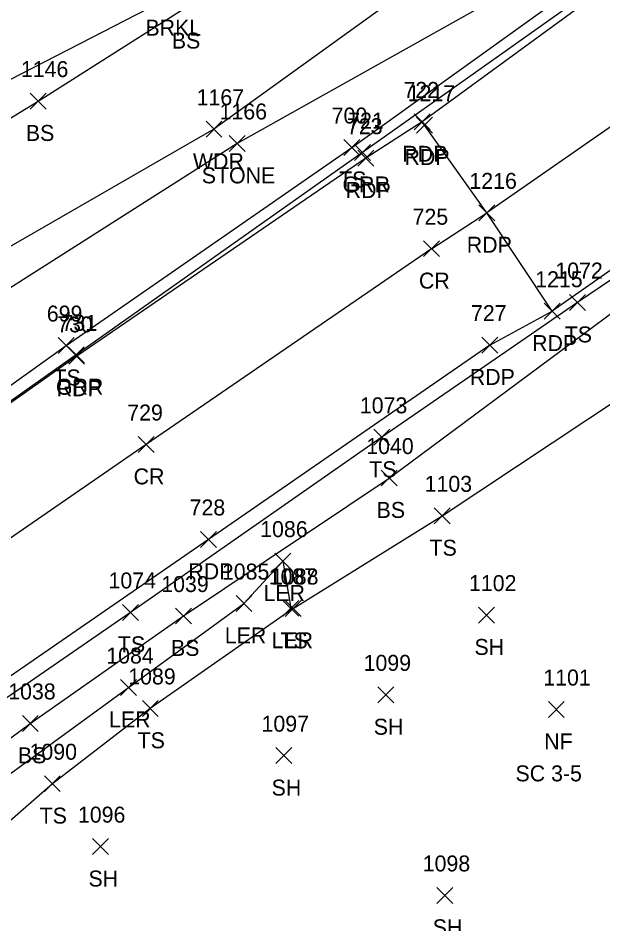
# Model space of a CAD drawing. Extents: x 1528286 to 1556263, y 492387 to 508952.
# Drawn here: x 1528736.9 to 1528810.2, y 492794 to 492907.5 of the extents above; entities that cross this region are included whole.
import ezdxf

# ---------------------------------------------------------------- set-up
doc = ezdxf.new("R2010")
doc.units = 0
for name, color, linetype in [('L_A', 7, 'Continuous'), ('L_C', 7, 'Continuous'), ('L_I', 7, 'Continuous'), ('L_TIC', 7, 'Continuous'), ('LARO', 7, 'Continuous'), ('LASF', 7, 'Continuous'), ('LAWA', 7, 'Continuous'), ('LAWE', 7, 'Continuous'), ('LELB', 7, 'Continuous'), ('P_A', 7, 'Continuous'), ('P_I', 7, 'Continuous'), ('P_TIC', 7, 'Continuous'), ('PET', 7, 'Continuous'), ('PRC', 7, 'Continuous'), ('R_A', 7, 'Continuous'), ('R_I', 7, 'Continuous'), ('R_TIC', 7, 'Continuous'), ('RGR', 7, 'Continuous')]:
    doc.layers.add(name, color=color, linetype=linetype)

msp = doc.modelspace()

# ---------------------------------------------------------------- linework, layer by layer
at = {"layer": 'L_TIC'}
for points in [[(1528738.42, 492896.09), (1528740.42, 492898.09)], [(1528740.42, 492896.09), (1528738.42, 492898.09)], [(1528738.42, 492896.09), (1528740.42, 492898.09)], [(1528740.42, 492896.09), (1528738.42, 492898.09)], [(1528760.44, 492892.56), (1528762.44, 492894.56)], [(1528762.44, 492892.56), (1528760.44, 492894.56)], [(1528760.44, 492892.56), (1528762.44, 492894.56)], [(1528762.44, 492892.56), (1528760.44, 492894.56)], [(1528763.36, 492890.78), (1528765.36, 492892.78)], [(1528765.36, 492890.78), (1528763.36, 492892.78)], [(1528763.36, 492890.78), (1528765.36, 492892.78)], [(1528765.36, 492890.78), (1528763.36, 492892.78)], [(1528777.71, 492890.27), (1528779.71, 492892.27)], [(1528779.71, 492890.27), (1528777.71, 492892.27)], [(1528777.71, 492890.27), (1528779.71, 492892.27)], [(1528779.71, 492890.27), (1528777.71, 492892.27)], [(1528805.99, 492870.86), (1528807.99, 492872.86)], [(1528807.99, 492870.86), (1528805.99, 492872.86)], [(1528805.99, 492870.86), (1528807.99, 492872.86)], [(1528807.99, 492870.86), (1528805.99, 492872.86)], [(1528741.91, 492865.47), (1528743.91, 492867.47)], [(1528743.91, 492865.47), (1528741.91, 492867.47)], [(1528741.91, 492865.47), (1528743.91, 492867.47)], [(1528743.91, 492865.47), (1528741.91, 492867.47)], [(1528781.49, 492853.98), (1528783.49, 492855.98)], [(1528783.49, 492853.98), (1528781.49, 492855.98)], [(1528781.49, 492853.98), (1528783.49, 492855.98)], [(1528783.49, 492853.98), (1528781.49, 492855.98)], [(1528782.38, 492848.88), (1528784.38, 492850.88)], [(1528784.38, 492848.88), (1528782.38, 492850.88)], [(1528782.38, 492848.88), (1528784.38, 492850.88)], [(1528784.38, 492848.88), (1528782.38, 492850.88)], [(1528789.05, 492844.15), (1528791.05, 492846.15)], [(1528791.05, 492844.15), (1528789.05, 492846.15)], [(1528789.05, 492844.15), (1528791.05, 492846.15)], [(1528791.05, 492844.15), (1528789.05, 492846.15)], [(1528769.06, 492838.48), (1528771.06, 492840.48)], [(1528771.06, 492838.48), (1528769.06, 492840.48)], [(1528769.06, 492838.48), (1528771.06, 492840.48)], [(1528771.06, 492838.48), (1528769.06, 492840.48)], [(1528764.2, 492833.16), (1528766.2, 492835.16)], [(1528766.2, 492833.16), (1528764.2, 492835.16)], [(1528764.2, 492833.16), (1528766.2, 492835.16)], [(1528766.2, 492833.16), (1528764.2, 492835.16)], [(1528749.99, 492832.05), (1528751.99, 492834.05)], [(1528751.99, 492832.05), (1528749.99, 492834.05)], [(1528749.99, 492832.05), (1528751.99, 492834.05)], [(1528751.99, 492832.05), (1528749.99, 492834.05)], [(1528756.61, 492831.6), (1528758.61, 492833.6)], [(1528758.61, 492831.6), (1528756.61, 492833.6)], [(1528756.61, 492831.6), (1528758.61, 492833.6)], [(1528758.61, 492831.6), (1528756.61, 492833.6)], [(1528770.07, 492832.56), (1528772.07, 492834.56)], [(1528772.07, 492832.56), (1528770.07, 492834.56)], [(1528770.07, 492832.56), (1528772.07, 492834.56)], [(1528772.07, 492832.56), (1528770.07, 492834.56)], [(1528770.37, 492832.54), (1528772.37, 492834.54)], [(1528772.37, 492832.54), (1528770.37, 492834.54)], [(1528770.37, 492832.54), (1528772.37, 492834.54)], [(1528772.37, 492832.54), (1528770.37, 492834.54)], [(1528770.37, 492832.54), (1528772.37, 492834.54)], [(1528772.37, 492832.54), (1528770.37, 492834.54)], [(1528770.37, 492832.54), (1528772.37, 492834.54)], [(1528772.37, 492832.54), (1528770.37, 492834.54)], [(1528794.6, 492831.72), (1528796.6, 492833.72)], [(1528796.6, 492831.72), (1528794.6, 492833.72)], [(1528794.6, 492831.72), (1528796.6, 492833.72)], [(1528796.6, 492831.72), (1528794.6, 492833.72)], [(1528749.71, 492822.64), (1528751.71, 492824.64)], [(1528751.71, 492822.64), (1528749.71, 492824.64)], [(1528749.71, 492822.64), (1528751.71, 492824.64)], [(1528751.71, 492822.64), (1528749.71, 492824.64)], [(1528781.97, 492821.73), (1528783.97, 492823.73)], [(1528783.97, 492821.73), (1528781.97, 492823.73)], [(1528781.97, 492821.73), (1528783.97, 492823.73)], [(1528783.97, 492821.73), (1528781.97, 492823.73)], [(1528752.46, 492820.03), (1528754.46, 492822.03)], [(1528754.46, 492820.03), (1528752.46, 492822.03)], [(1528752.46, 492820.03), (1528754.46, 492822.03)], [(1528754.46, 492820.03), (1528752.46, 492822.03)], [(1528803.35, 492819.89), (1528805.35, 492821.89)], [(1528805.35, 492819.89), (1528803.35, 492821.89)], [(1528803.35, 492819.89), (1528805.35, 492821.89)], [(1528805.35, 492819.89), (1528803.35, 492821.89)], [(1528737.42, 492818.15), (1528739.42, 492820.15)], [(1528739.42, 492818.15), (1528737.42, 492820.15)], [(1528737.42, 492818.15), (1528739.42, 492820.15)], [(1528739.42, 492818.15), (1528737.42, 492820.15)], [(1528769.18, 492814.11), (1528771.18, 492816.11)], [(1528771.18, 492814.11), (1528769.18, 492816.11)], [(1528769.18, 492814.11), (1528771.18, 492816.11)], [(1528771.18, 492814.11), (1528769.18, 492816.11)], [(1528740.18, 492810.6), (1528742.18, 492812.6)], [(1528742.18, 492810.6), (1528740.18, 492812.6)], [(1528740.18, 492810.6), (1528742.18, 492812.6)], [(1528742.18, 492810.6), (1528740.18, 492812.6)], [(1528746.22, 492802.72), (1528748.22, 492804.72)], [(1528748.22, 492802.72), (1528746.22, 492804.72)], [(1528746.22, 492802.72), (1528748.22, 492804.72)], [(1528748.22, 492802.72), (1528746.22, 492804.72)], [(1528789.37, 492796.61), (1528791.37, 492798.61)], [(1528791.37, 492796.61), (1528789.37, 492798.61)], [(1528789.37, 492796.61), (1528791.37, 492798.61)], [(1528791.37, 492796.61), (1528789.37, 492798.61)]]:
    msp.add_lwpolyline(points, dxfattribs=at)
at = {"layer": 'LARO'}
msp.add_lwpolyline([(1528721.39, 492800.54), (1528726.2, 492809.49), (1528731.9, 492809.97), (1528750.71, 492823.64), (1528765.2, 492834.16), (1528770.06, 492839.48), (1528771.07, 492833.56)], dxfattribs=at)
msp.add_lwpolyline([(1528721.39, 492800.54), (1528726.2, 492809.49), (1528731.9, 492809.97), (1528750.71, 492823.64), (1528765.2, 492834.16), (1528770.06, 492839.48), (1528771.07, 492833.56)], dxfattribs=at)
at = {"layer": 'LASF'}
msp.add_lwpolyline([(1528803.2, 492913.58), (1528764.36, 492891.78), (1528731.57, 492870.94), (1528716.56, 492864.1)], dxfattribs=at)
msp.add_lwpolyline([(1528803.2, 492913.58), (1528764.36, 492891.78), (1528731.57, 492870.94), (1528716.56, 492864.1)], dxfattribs=at)
at = {"layer": 'LAWA'}
msp.add_lwpolyline([(1528932.82, 493004.86), (1528877.3, 492973.44), (1528838.45, 492947.79), (1528805.62, 492925.4), (1528761.44, 492893.56), (1528731.58, 492876.41)], dxfattribs=at)
msp.add_lwpolyline([(1528932.82, 493004.86), (1528877.3, 492973.44), (1528838.45, 492947.79), (1528805.62, 492925.4), (1528761.44, 492893.56), (1528731.58, 492876.41)], dxfattribs=at)
at = {"layer": 'LAWE'}
msp.add_lwpolyline([(1528699.7, 492858.91), (1528705.19, 492868.42), (1528711.6, 492880.33), (1528733.01, 492898.34), (1528756.21, 492910.28), (1528789.07, 492931.12), (1528812.92, 492945.76), (1528839.47, 492958.79)], dxfattribs=at)
msp.add_lwpolyline([(1528699.7, 492858.91), (1528705.19, 492868.42), (1528711.6, 492880.33), (1528733.01, 492898.34), (1528756.21, 492910.28), (1528789.07, 492931.12), (1528812.92, 492945.76), (1528839.47, 492958.79)], dxfattribs=at)
at = {"layer": 'LELB'}
for points in [[(1528511.53, 492702.85), (1528534.14, 492721.31), (1528572.64, 492751.16), (1528586.73, 492763.59), (1528600.5, 492766.35), (1528613.46, 492775.52), (1528652.2, 492802.53), (1528688.62, 492828.26), (1528710.29, 492843.12), (1528742.91, 492866.47), (1528778.71, 492891.27), (1528817.45, 492919.08), (1528857.75, 492946.94), (1528897.37, 492973.98), (1528940.29, 493003.74)], [(1528511.53, 492702.85), (1528534.14, 492721.31), (1528572.64, 492751.16), (1528586.73, 492763.59), (1528600.5, 492766.35), (1528613.46, 492775.52), (1528652.2, 492802.53), (1528688.62, 492828.26), (1528710.29, 492843.12), (1528742.91, 492866.47), (1528778.71, 492891.27), (1528817.45, 492919.08), (1528857.75, 492946.94), (1528897.37, 492973.98), (1528940.29, 493003.74)], [(1528716.33, 492882.99), (1528739.42, 492897.09), (1528757.72, 492908.66), (1528787.4, 492928.88), (1528815.35, 492943.52), (1528839.47, 492958.79)], [(1528716.33, 492882.99), (1528739.42, 492897.09), (1528757.72, 492908.66), (1528787.4, 492928.88), (1528815.35, 492943.52), (1528839.47, 492958.79)], [(1528946.97, 492932.59), (1528919.96, 492926.16), (1528896.4, 492920.64), (1528892.93, 492919.08), (1528869.96, 492910.98), (1528843.06, 492896.38), (1528834.23, 492890.27), (1528806.99, 492871.86), (1528782.49, 492854.98), (1528750.99, 492833.05), (1528710.78, 492805.36), (1528694.19, 492792.45), (1528682.22, 492773.58), (1528672.78, 492775.79)], [(1528946.97, 492932.59), (1528919.96, 492926.16), (1528896.4, 492920.64), (1528892.93, 492919.08), (1528869.96, 492910.98), (1528843.06, 492896.38), (1528834.23, 492890.27), (1528806.99, 492871.86), (1528782.49, 492854.98), (1528750.99, 492833.05), (1528710.78, 492805.36), (1528694.19, 492792.45), (1528682.22, 492773.58), (1528672.78, 492775.79)], [(1528771.37, 492833.54), (1528790.05, 492845.15), (1528813.01, 492860.36), (1528823.16, 492868.5), (1528838.74, 492881.76), (1528852.78, 492883.19), (1528874.04, 492896.82), (1528872.11, 492886.31)], [(1528771.37, 492833.54), (1528790.05, 492845.15), (1528813.01, 492860.36), (1528823.16, 492868.5), (1528838.74, 492881.76), (1528852.78, 492883.19), (1528874.04, 492896.82), (1528872.11, 492886.31)], [(1528675.2, 492746.9), (1528689.3, 492770.43), (1528699.75, 492780.85), (1528706.23, 492795.33), (1528738.42, 492819.15), (1528757.61, 492832.6), (1528783.38, 492849.88), (1528832.02, 492885.93)], [(1528675.2, 492746.9), (1528689.3, 492770.43), (1528699.75, 492780.85), (1528706.23, 492795.33), (1528738.42, 492819.15), (1528757.61, 492832.6), (1528783.38, 492849.88), (1528832.02, 492885.93)], [(1528771.37, 492833.54), (1528753.46, 492821.03), (1528741.18, 492811.6), (1528730.18, 492801.97), (1528717.83, 492786.84)], [(1528771.37, 492833.54), (1528753.46, 492821.03), (1528741.18, 492811.6), (1528730.18, 492801.97), (1528717.83, 492786.84)]]:
    msp.add_lwpolyline(points, dxfattribs=at)
at = {"layer": 'P_TIC'}
for points in [[(1528786.55, 492893.48), (1528788.55, 492895.48)], [(1528788.55, 492893.48), (1528786.55, 492895.48)], [(1528786.55, 492893.48), (1528788.55, 492895.48)], [(1528788.55, 492893.48), (1528786.55, 492895.48)], [(1528786.84, 492893.07), (1528788.84, 492895.07)], [(1528788.84, 492893.07), (1528786.84, 492895.07)], [(1528786.84, 492893.07), (1528788.84, 492895.07)], [(1528788.84, 492893.07), (1528786.84, 492895.07)], [(1528779.46, 492888.94), (1528781.46, 492890.94)], [(1528781.46, 492888.94), (1528779.46, 492890.94)], [(1528779.46, 492888.94), (1528781.46, 492890.94)], [(1528781.46, 492888.94), (1528779.46, 492890.94)], [(1528794.63, 492882.09), (1528796.63, 492884.09)], [(1528796.63, 492882.09), (1528794.63, 492884.09)], [(1528794.63, 492882.09), (1528796.63, 492884.09)], [(1528796.63, 492882.09), (1528794.63, 492884.09)], [(1528787.69, 492877.6), (1528789.69, 492879.6)], [(1528789.69, 492877.6), (1528787.69, 492879.6)], [(1528787.69, 492877.6), (1528789.69, 492879.6)], [(1528789.69, 492877.6), (1528787.69, 492879.6)], [(1528802.83, 492869.77), (1528804.83, 492871.77)], [(1528804.83, 492869.77), (1528802.83, 492871.77)], [(1528802.83, 492869.77), (1528804.83, 492871.77)], [(1528804.83, 492869.77), (1528802.83, 492871.77)], [(1528795.01, 492865.53), (1528797.01, 492867.53)], [(1528797.01, 492865.53), (1528795.01, 492867.53)], [(1528795.01, 492865.53), (1528797.01, 492867.53)], [(1528797.01, 492865.53), (1528795.01, 492867.53)], [(1528743.23, 492864.12), (1528745.23, 492866.12)], [(1528745.23, 492864.12), (1528743.23, 492866.12)], [(1528743.23, 492864.12), (1528745.23, 492866.12)], [(1528745.23, 492864.12), (1528743.23, 492866.12)], [(1528751.94, 492853.08), (1528753.94, 492855.08)], [(1528753.94, 492853.08), (1528751.94, 492855.08)], [(1528751.94, 492853.08), (1528753.94, 492855.08)], [(1528753.94, 492853.08), (1528751.94, 492855.08)], [(1528759.74, 492841.19), (1528761.74, 492843.19)], [(1528761.74, 492841.19), (1528759.74, 492843.19)], [(1528759.74, 492841.19), (1528761.74, 492843.19)], [(1528761.74, 492841.19), (1528759.74, 492843.19)]]:
    msp.add_lwpolyline(points, dxfattribs=at)
at = {"layer": 'PET'}
for points in [[(1528942, 493002.12), (1528898.48, 492972.51), (1528859.28, 492945.34), (1528819.08, 492917.53), (1528787.55, 492894.48), (1528780.46, 492889.94), (1528744.23, 492865.12), (1528711.17, 492841.82), (1528689.56, 492826.66), (1528653.33, 492801.52)], [(1528942, 493002.12), (1528898.48, 492972.51), (1528859.28, 492945.34), (1528819.08, 492917.53), (1528787.55, 492894.48), (1528780.46, 492889.94), (1528744.23, 492865.12), (1528711.17, 492841.82), (1528689.56, 492826.66), (1528653.33, 492801.52)], [(1528787.84, 492894.07), (1528787.55, 492894.48)], [(1528787.84, 492894.07), (1528787.55, 492894.48)], [(1528803.83, 492870.77), (1528795.63, 492883.09), (1528787.84, 492894.07)], [(1528803.83, 492870.77), (1528795.63, 492883.09), (1528787.84, 492894.07)], [(1528835.6, 492893.02), (1528803.83, 492870.77)], [(1528835.6, 492893.02), (1528803.83, 492870.77)], [(1528796.01, 492866.53), (1528803.83, 492870.77)], [(1528796.01, 492866.53), (1528803.83, 492870.77)], [(1528796.01, 492866.53), (1528760.74, 492842.19), (1528727.56, 492819.31), (1528705.98, 492804.17), (1528668.89, 492778.39)], [(1528796.01, 492866.53), (1528760.74, 492842.19), (1528727.56, 492819.31), (1528705.98, 492804.17), (1528668.89, 492778.39)]]:
    msp.add_lwpolyline(points, dxfattribs=at)
at = {"layer": 'PRC'}
for points in [[(1528827.79, 492905.43), (1528795.63, 492883.09)], [(1528827.79, 492905.43), (1528795.63, 492883.09)], [(1528788.69, 492878.6), (1528795.63, 492883.09)], [(1528788.69, 492878.6), (1528795.63, 492883.09)], [(1528788.69, 492878.6), (1528752.94, 492854.08), (1528719.05, 492830.75), (1528697.88, 492816.16), (1528660.71, 492790.64)], [(1528788.69, 492878.6), (1528752.94, 492854.08), (1528719.05, 492830.75), (1528697.88, 492816.16), (1528660.71, 492790.64)]]:
    msp.add_lwpolyline(points, dxfattribs=at)
at = {"layer": 'R_TIC'}
for points in [[(1528779.05, 492889.64), (1528781.05, 492891.64)], [(1528781.05, 492889.64), (1528779.05, 492891.64)], [(1528779.05, 492889.64), (1528781.05, 492891.64)], [(1528781.05, 492889.64), (1528779.05, 492891.64)], [(1528743.15, 492864.31), (1528745.15, 492866.31)], [(1528745.15, 492864.31), (1528743.15, 492866.31)], [(1528743.15, 492864.31), (1528745.15, 492866.31)], [(1528745.15, 492864.31), (1528743.15, 492866.31)]]:
    msp.add_lwpolyline(points, dxfattribs=at)
at = {"layer": 'RGR'}
msp.add_lwpolyline([(1528941.4, 493002.79), (1528898.12, 492973.22), (1528858.97, 492945.9), (1528818.83, 492918.12), (1528780.05, 492890.64), (1528744.15, 492865.31), (1528711.24, 492842.07), (1528689.6, 492826.87), (1528653.3, 492801.62)], dxfattribs=at)
msp.add_lwpolyline([(1528941.4, 493002.79), (1528898.12, 492973.22), (1528858.97, 492945.9), (1528818.83, 492918.12), (1528780.05, 492890.64), (1528744.15, 492865.31), (1528711.24, 492842.07), (1528689.6, 492826.87), (1528653.3, 492801.62)], dxfattribs=at)

# ---------------------------------------------------------------- texts
at = {"layer": 'L_A'}
for s, p in [('BRKL', (1528752.85, 492905.28)), ('BRKL', (1528752.85, 492905.28)), ('BS', (1528756.16, 492903.66)), ('BS', (1528756.16, 492903.66)), ('BS', (1528737.86, 492892.09)), ('BS', (1528737.86, 492892.09)), ('WDR', (1528758.8, 492888.56)), ('WDR', (1528758.8, 492888.56)), ('STONE', (1528759.91, 492886.78)), ('STONE', (1528759.91, 492886.78)), ('TS', (1528777.12, 492886.27)), ('TS', (1528777.12, 492886.27)), ('TS', (1528805.4, 492866.86)), ('TS', (1528805.4, 492866.86)), ('TS', (1528741.32, 492861.47)), ('TS', (1528741.32, 492861.47)), ('TS', (1528780.9, 492849.98)), ('TS', (1528780.9, 492849.98)), ('BS', (1528781.82, 492844.88)), ('BS', (1528781.82, 492844.88)), ('TS', (1528788.46, 492840.15)), ('TS', (1528788.46, 492840.15)), ('LER', (1528767.64, 492834.48)), ('LER', (1528767.64, 492834.48)), ('LER', (1528762.79, 492829.16)), ('LER', (1528762.79, 492829.16)), ('LER', (1528768.65, 492828.56)), ('LER', (1528768.65, 492828.56)), ('TS', (1528769.77, 492828.54)), ('TS', (1528769.77, 492828.54)), ('TS', (1528769.77, 492828.54)), ('TS', (1528769.77, 492828.54)), ('TS', (1528749.4, 492828.05)), ('TS', (1528749.4, 492828.05)), ('BS', (1528756.05, 492827.6)), ('BS', (1528756.05, 492827.6)), ('SH', (1528794.09, 492827.72)), ('SH', (1528794.09, 492827.72)), ('LER', (1528748.29, 492818.64)), ('LER', (1528748.29, 492818.64)), ('SH', (1528781.46, 492817.73)), ('SH', (1528781.46, 492817.73)), ('TS', (1528751.87, 492816.03)), ('TS', (1528751.87, 492816.03)), ('NF', (1528802.83, 492815.89)), ('NF', (1528802.83, 492815.89)), ('BS', (1528736.86, 492814.15)), ('BS', (1528736.86, 492814.15)), ('SH', (1528768.66, 492810.11)), ('SH', (1528768.66, 492810.11)), ('TS', (1528739.59, 492806.6)), ('TS', (1528739.59, 492806.6)), ('SH', (1528745.71, 492798.72)), ('SH', (1528745.71, 492798.72)), ('SH', (1528788.86, 492792.61)), ('SH', (1528788.86, 492792.61))]:
    msp.add_text(s, height=2, dxfattribs=at).set_placement(p)
at = {"layer": 'L_C'}
msp.add_text('SC 3-5', height=2, dxfattribs=at).set_placement((1528799.23, 492811.89))
msp.add_text('SC 3-5', height=2, dxfattribs=at).set_placement((1528799.23, 492811.89))
at = {"layer": 'L_I'}
for s, p in [('1146', (1528737.24, 492900.09)), ('1146', (1528737.24, 492900.09)), ('1167', (1528759.26, 492896.56)), ('1167', (1528759.26, 492896.56)), ('1166', (1528762.14, 492894.78)), ('1166', (1528762.14, 492894.78)), ('700', (1528776.19, 492894.27)), ('700', (1528776.19, 492894.27)), ('1072', (1528804.22, 492874.86)), ('1072', (1528804.22, 492874.86)), ('699', (1528740.49, 492869.47)), ('699', (1528740.49, 492869.47)), ('1073', (1528779.72, 492857.98)), ('1073', (1528779.72, 492857.98)), ('1040', (1528780.52, 492852.88)), ('1040', (1528780.52, 492852.88)), ('1103', (1528787.84, 492848.15)), ('1103', (1528787.84, 492848.15)), ('1086', (1528767.23, 492842.48)), ('1086', (1528767.23, 492842.48)), ('1085', (1528762.43, 492837.16)), ('1085', (1528762.43, 492837.16)), ('1087', (1528768.3, 492836.56)), ('1087', (1528768.3, 492836.56)), ('1088', (1528768.59, 492836.54)), ('1088', (1528768.59, 492836.54)), ('1088', (1528768.59, 492836.54)), ('1088', (1528768.59, 492836.54)), ('1074', (1528748.22, 492836.05)), ('1074', (1528748.22, 492836.05)), ('1039', (1528754.83, 492835.6)), ('1039', (1528754.83, 492835.6)), ('1102', (1528793.4, 492835.72)), ('1102', (1528793.4, 492835.72)), ('1084', (1528747.94, 492826.64)), ('1084', (1528747.94, 492826.64)), ('1099', (1528780.19, 492825.73)), ('1099', (1528780.19, 492825.73)), ('1089', (1528750.69, 492824.03)), ('1089', (1528750.69, 492824.03)), ('1101', (1528802.71, 492823.89)), ('1101', (1528802.71, 492823.89)), ('1038', (1528735.65, 492822.15)), ('1038', (1528735.65, 492822.15)), ('1097', (1528767.4, 492818.11)), ('1097', (1528767.4, 492818.11)), ('1090', (1528738.32, 492814.6)), ('1090', (1528738.32, 492814.6)), ('1096', (1528744.39, 492806.72)), ('1096', (1528744.39, 492806.72)), ('1098', (1528787.6, 492800.61)), ('1098', (1528787.6, 492800.61))]:
    msp.add_text(s, height=2, dxfattribs=at).set_placement(p)
at = {"layer": 'P_A'}
for s, p in [('RDP', (1528785.04, 492889.48)), ('RDP', (1528785.04, 492889.48)), ('RDP', (1528785.32, 492889.07)), ('RDP', (1528785.32, 492889.07)), ('RDP', (1528777.95, 492884.94)), ('RDP', (1528777.95, 492884.94)), ('RDP', (1528793.12, 492878.09)), ('RDP', (1528793.12, 492878.09)), ('CR', (1528787.13, 492873.6)), ('CR', (1528787.13, 492873.6)), ('RDP', (1528801.31, 492865.77)), ('RDP', (1528801.31, 492865.77)), ('RDP', (1528793.5, 492861.53)), ('RDP', (1528793.5, 492861.53)), ('RDP', (1528741.72, 492860.12)), ('RDP', (1528741.72, 492860.12)), ('CR', (1528751.37, 492849.08)), ('CR', (1528751.37, 492849.08)), ('RDP', (1528758.23, 492837.19)), ('RDP', (1528758.23, 492837.19))]:
    msp.add_text(s, height=2, dxfattribs=at).set_placement(p)
at = {"layer": 'P_I'}
for s, p in [('722', (1528785.19, 492897.48)), ('722', (1528785.19, 492897.48)), ('1217', (1528785.71, 492897.07)), ('1217', (1528785.71, 492897.07)), ('723', (1528778.1, 492892.94)), ('723', (1528778.1, 492892.94)), ('1216', (1528793.45, 492886.09)), ('1216', (1528793.45, 492886.09)), ('725', (1528786.33, 492881.6)), ('725', (1528786.33, 492881.6)), ('1215', (1528801.7, 492873.77)), ('1215', (1528801.7, 492873.77)), ('727', (1528793.65, 492869.53)), ('727', (1528793.65, 492869.53)), ('730', (1528741.78, 492868.12)), ('730', (1528741.78, 492868.12)), ('729', (1528750.57, 492857.08)), ('729', (1528750.57, 492857.08)), ('728', (1528758.38, 492845.19)), ('728', (1528758.38, 492845.19))]:
    msp.add_text(s, height=2, dxfattribs=at).set_placement(p)
at = {"layer": 'R_A'}
for p in [(1528777.54, 492885.64), (1528777.54, 492885.64), (1528741.63, 492860.31), (1528741.63, 492860.31)]:
    msp.add_text('GRR', height=2, dxfattribs=at).set_placement(p)
at = {"layer": 'R_I'}
for s, p in [('721', (1528778.26, 492893.64)), ('721', (1528778.26, 492893.64)), ('731', (1528742.35, 492868.31)), ('731', (1528742.35, 492868.31))]:
    msp.add_text(s, height=2, dxfattribs=at).set_placement(p)

doc.saveas('drawing.dxf')
